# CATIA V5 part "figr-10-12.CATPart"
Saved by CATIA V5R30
Part number: Part1
Bounding box of the stored display mesh (mm): x -100 to 0, y -100 to 90, z 0 to 33.63
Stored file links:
  D:\PROJECTS\CATIA V56R 2020\Resources\Parts File\c10_catia_v5_6r2020_prt\figr-10-12.CATPart
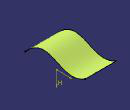
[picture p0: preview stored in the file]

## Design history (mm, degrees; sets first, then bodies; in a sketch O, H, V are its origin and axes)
Set1
  Sketch1 on face of yz-plane, origin (0, 0, 0), H (0, 0, -1), V (0, 1, 0)
    spline S1 through (0, -100) (-30, -20) (-10, 30) (-20, 90)
  Extrude1: Element1 Sketch1, Lim1 0, Lim2 100, Direction face of yz-plane
Body1 (main body)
